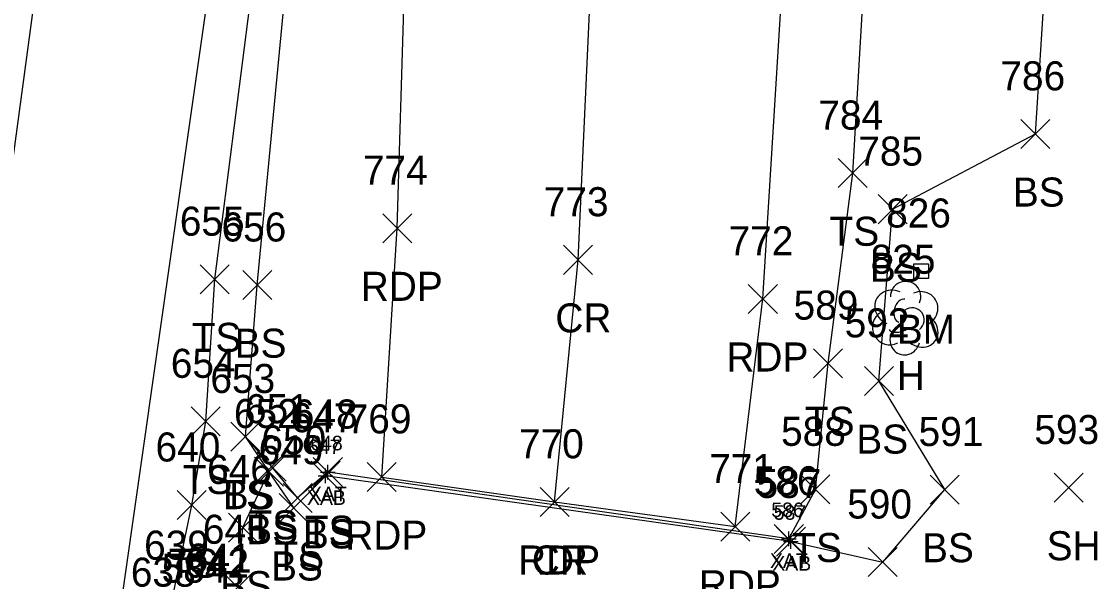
# Model space of a CAD drawing. Extents: x 1482574 to 1485769, y 580696 to 595649.
# Drawn here: x 1483671.3 to 1483745.3, y 584459.2 to 584497.7 of the extents above; entities that cross this region are included whole.
import ezdxf

# ---------------------------------------------------------------- set-up
doc = ezdxf.new("R2010")
doc.units = 0
for name, color, linetype in [('B_A', 7, 'Continuous'), ('B_I', 7, 'Continuous'), ('B_TIC', 7, 'Continuous'), ('BSUBM', 7, 'Continuous'), ('C_A', 7, 'Continuous'), ('C_I', 7, 'Continuous'), ('CPBM', 7, 'Continuous'), ('D_I', 7, 'Continuous'), ('L_A', 7, 'Continuous'), ('L_I', 7, 'Continuous'), ('L_TIC', 7, 'Continuous'), ('LELB', 7, 'Continuous'), ('LTD', 7, 'Continuous'), ('P_A', 7, 'Continuous'), ('P_I', 7, 'Continuous'), ('P_TIC', 7, 'Continuous'), ('PET', 7, 'Continuous'), ('PRC', 7, 'Continuous')]:
    doc.layers.add(name, color=color, linetype=linetype)

msp = doc.modelspace()

# ---------------------------------------------------------------- linework, layer by layer
at = {"layer": 'B_TIC'}
for p, q in [((1483692.191, 584466.458), (1483692.266, 584466.458)), ((1483692.345, 584466.713), (1483692.421, 584466.713)), ((1483724.085, 584462.117), (1483724.161, 584462.117)), ((1483724.226, 584461.933), (1483724.301, 584461.933))]:
    msp.add_line(p, q, dxfattribs=at)
for points in [[(1483692.342, 584466.213), (1483692.342, 584467.213)], [(1483691.687, 584466.458), (1483692.687, 584466.458)], [(1483691.842, 584466.713), (1483692.842, 584466.713)], [(1483692.187, 584465.958), (1483692.187, 584466.958)], [(1483723.582, 584462.117), (1483724.582, 584462.117)], [(1483724.082, 584461.617), (1483724.082, 584462.617)], [(1483724.222, 584461.433), (1483724.222, 584462.433)], [(1483723.722, 584461.933), (1483724.722, 584461.933)]]:
    msp.add_lwpolyline(points, dxfattribs=at)
at = {"layer": 'BSUBM'}
for points in [[(1483724.222, 584461.933), (1483692.187, 584466.458)], [(1483724.082, 584462.117), (1483692.342, 584466.713)]]:
    msp.add_lwpolyline(points, dxfattribs=at)
at = {"layer": 'CPBM'}
for p, q in [((1483732.691, 584480.051), (1483732.691, 584481.052)), ((1483732.691, 584481.052), (1483733.691, 584481.052)), ((1483733.194, 584480.552), (1483733.194, 584480.552)), ((1483733.194, 584480.552), (1483733.194, 584480.552)), ((1483733.691, 584481.052), (1483733.691, 584480.051)), ((1483733.691, 584480.051), (1483732.691, 584480.051))]:
    msp.add_line(p, q, dxfattribs=at)
at = {"layer": 'L_TIC'}
for points in [[(1483740.06, 584488.994), (1483742.06, 584490.994)], [(1483742.06, 584488.994), (1483740.06, 584490.994)], [(1483727.475, 584486.296), (1483729.475, 584488.296)], [(1483729.475, 584486.296), (1483727.475, 584488.296)], [(1483730.223, 584483.814), (1483732.223, 584485.814)], [(1483732.223, 584483.814), (1483730.223, 584485.814)], [(1483683.56, 584478.99), (1483685.56, 584480.99)], [(1483685.56, 584478.99), (1483683.56, 584480.99)], [(1483686.487, 584478.59), (1483688.487, 584480.59)], [(1483688.487, 584478.59), (1483686.487, 584480.59)], [(1483686.487, 584478.59), (1483688.487, 584480.59)], [(1483688.487, 584478.59), (1483686.487, 584480.59)], [(1483725.778, 584473.21), (1483727.778, 584475.21)], [(1483727.778, 584473.21), (1483725.778, 584475.21)], [(1483729.285, 584471.988), (1483731.285, 584473.988)], [(1483731.285, 584471.988), (1483729.285, 584473.988)], [(1483682.941, 584469.204), (1483684.941, 584471.204)], [(1483684.941, 584469.204), (1483682.941, 584471.204)], [(1483685.666, 584468.162), (1483687.666, 584470.162)], [(1483687.666, 584468.162), (1483685.666, 584470.162)], [(1483685.666, 584468.162), (1483687.666, 584470.162)], [(1483687.666, 584468.162), (1483685.666, 584470.162)], [(1483687.48, 584466.081), (1483689.48, 584468.081)], [(1483689.48, 584466.081), (1483687.48, 584468.081)], [(1483687.287, 584465.751), (1483689.287, 584467.751)], [(1483689.287, 584465.751), (1483687.287, 584467.751)], [(1483687.287, 584465.751), (1483689.287, 584467.751)], [(1483689.287, 584465.751), (1483687.287, 584467.751)], [(1483691.187, 584465.458), (1483693.187, 584467.458)], [(1483693.187, 584465.458), (1483691.187, 584467.458)], [(1483691.342, 584465.713), (1483693.342, 584467.713)], [(1483693.342, 584465.713), (1483691.342, 584467.713)], [(1483724.907, 584464.522), (1483726.907, 584466.522)], [(1483726.907, 584464.522), (1483724.907, 584466.522)], [(1483733.809, 584464.509), (1483735.809, 584466.509)], [(1483735.809, 584464.509), (1483733.809, 584466.509)], [(1483742.344, 584464.645), (1483744.344, 584466.645)], [(1483744.344, 584464.645), (1483742.344, 584466.645)], [(1483689.264, 584463.932), (1483691.264, 584465.932)], [(1483691.264, 584463.932), (1483689.264, 584465.932)], [(1483681.978, 584463.444), (1483683.978, 584465.444)], [(1483683.978, 584463.444), (1483681.978, 584465.444)], [(1483688.995, 584463.25), (1483690.995, 584465.25)], [(1483690.995, 584463.25), (1483688.995, 584465.25)], [(1483685.493, 584461.897), (1483687.493, 584463.897)], [(1483687.493, 584461.897), (1483685.493, 584463.897)], [(1483723.082, 584461.117), (1483725.082, 584463.117)], [(1483725.082, 584461.117), (1483723.082, 584463.117)], [(1483723.222, 584460.933), (1483725.222, 584462.933)], [(1483725.222, 584460.933), (1483723.222, 584462.933)], [(1483729.548, 584459.517), (1483731.548, 584461.517)], [(1483731.548, 584459.517), (1483729.548, 584461.517)], [(1483685.145, 584457.78), (1483687.145, 584459.78)], [(1483687.145, 584457.78), (1483685.145, 584459.78)], [(1483685.145, 584457.78), (1483687.145, 584459.78)], [(1483687.145, 584457.78), (1483685.145, 584459.78)]]:
    msp.add_lwpolyline(points, dxfattribs=at)
at = {"layer": 'LELB'}
for points in [[(1483724.082, 584462.117), (1483725.907, 584465.522), (1483726.778, 584474.21), (1483728.475, 584487.296), (1483730.22, 584517.102), (1483728.729, 584547.617), (1483723.607, 584570.881), (1483719.45, 584596.971), (1483717.38, 584631.511), (1483714.685, 584660.925), (1483714.05, 584681.93), (1483713.087, 584704.559), (1483712.732, 584748.378), (1483712.013, 584794.586), (1483710.894, 584850.574), (1483709.946, 584870.249), (1483710.982, 584893.468), (1483715.858, 584918.494)], [(1483724.222, 584461.933), (1483730.548, 584460.517), (1483734.809, 584465.509), (1483730.285, 584472.988), (1483731.223, 584484.814), (1483741.06, 584489.994), (1483742.648, 584514.966), (1483736.695, 584548.75), (1483727.528, 584570.579), (1483723.616, 584597.151), (1483724.565, 584630.748), (1483719.544, 584660.803), (1483719.138, 584682.266)], [(1483681.19, 584455.828), (1483682.978, 584464.444), (1483683.941, 584470.204), (1483684.56, 584479.99), (1483687.932, 584506.357), (1483690.535, 584538.953), (1483691.613, 584557.814)], [(1483687.487, 584479.59), (1483690.015, 584506.184), (1483692.728, 584538.566), (1483691.613, 584557.814)], [(1483686.145, 584458.78), (1483686.493, 584462.897), (1483688.287, 584466.751), (1483686.666, 584469.162), (1483687.487, 584479.59)], [(1483692.342, 584466.713), (1483690.264, 584464.932), (1483688.48, 584467.081), (1483686.666, 584469.162)], [(1483692.187, 584466.458), (1483689.995, 584464.25), (1483688.287, 584466.751)]]:
    msp.add_lwpolyline(points, dxfattribs=at)
at = {"layer": 'LTD'}
msp.add_line((1483732.075, 584477.368), (1483732.075, 584477.368), dxfattribs=at)
msp.add_line((1483732.075, 584477.368), (1483732.075, 584477.368), dxfattribs=at)
msp.add_arc((1483732.122, 584478.802), 1.047, 335.52715, 180.95627, dxfattribs=at)
for centre, major_axis, ratio, start_param, end_param in [((1483731.283, 584478.034), (1.21, -0.512), 0.895232, 1.570796, 4.712389), ((1483733.116, 584477.951), (-1.141, -0.483), 0.949671, 1.570796, 4.712389), ((1483731.866, 584477.826), (-0.208, -0.792), 0.645439, 3.141593, 6.283185), ((1483730.992, 584476.659), (0.584, -1.042), 0.959034, 3.141593, 6.283185), ((1483732.575, 584477.201), (-0.5, 0.667), 0.989748, 3.141593, 6.283185), ((1483733.075, 584476.535), (-1.09, 0.792), 0.841452, 1.570796, 4.712389), ((1483732.075, 584475.868), (0.265, 1.061), 0.942809, 1.570796, 4.712389), ((1483731.617, 584476.618), (-0.625, -0.083), 0.423636, 0, 3.141593)]:
    msp.add_ellipse(centre, major_axis=major_axis, ratio=ratio, start_param=start_param, end_param=end_param, dxfattribs=at)
at = {"layer": 'P_TIC'}
for points in [[(1483696.12, 584482.504), (1483698.12, 584484.504)], [(1483698.12, 584482.504), (1483696.12, 584484.504)], [(1483708.571, 584480.329), (1483710.571, 584482.329)], [(1483710.571, 584480.329), (1483708.571, 584482.329)], [(1483721.292, 584477.639), (1483723.292, 584479.639)], [(1483723.292, 584477.639), (1483721.292, 584479.639)], [(1483695.056, 584465.376), (1483697.056, 584467.376)], [(1483697.056, 584465.376), (1483695.056, 584467.376)], [(1483695.056, 584465.376), (1483697.056, 584467.376)], [(1483697.056, 584465.376), (1483695.056, 584467.376)], [(1483706.951, 584463.664), (1483708.951, 584465.664)], [(1483708.951, 584463.664), (1483706.951, 584465.664)], [(1483706.951, 584463.664), (1483708.951, 584465.664)], [(1483708.951, 584463.664), (1483706.951, 584465.664)], [(1483719.395, 584461.958), (1483721.395, 584463.958)], [(1483721.395, 584461.958), (1483719.395, 584463.958)]]:
    msp.add_lwpolyline(points, dxfattribs=at)
at = {"layer": 'PET'}
for points in [[(1483696.056, 584466.376), (1483697.12, 584483.504), (1483698.012, 584513.546), (1483697.99, 584538.325), (1483692.768, 584571.081), (1483691.881, 584578.266), (1483689.767, 584596.032), (1483686.09, 584631.801), (1483683.963, 584666.864), (1483683.24, 584704.064), (1483683.213, 584748.185), (1483682.284, 584793.898), (1483680.781, 584850.652), (1483678.799, 584902.917), (1483672.318, 584970.596), (1483669.676, 585004.195), (1483663.897, 585069.156), (1483661.293, 585125.323), (1483656.933, 585178.041), (1483653.345, 585225.148), (1483650.718, 585274.261)], [(1483696.056, 584466.376), (1483707.951, 584464.664), (1483720.395, 584462.958), (1483722.292, 584478.639), (1483724.313, 584511.602), (1483723.072, 584540.322), (1483718.492, 584572.42), (1483715.109, 584598.08), (1483710.676, 584631.833), (1483709.971, 584663.072), (1483708.89, 584702.48), (1483708.909, 584747.528), (1483707.882, 584794.212), (1483706.23, 584850.223), (1483704.432, 584903.519), (1483701.567, 584959.324), (1483696.138, 585000.989), (1483691.089, 585058.765), (1483691.123, 585078.996), (1483685.882, 585127.238), (1483682.764, 585180.384), (1483679.267, 585226.938), (1483675.802, 585274.419)], [(1483647.153, 584246.073), (1483652.116, 584273.969), (1483655.812, 584298.407), (1483662.078, 584336.279), (1483668.628, 584381.649), (1483673.206, 584417.173), (1483676.95, 584449.388), (1483685.132, 584506.852), (1483688.619, 584539.157), (1483690.513, 584562.402), (1483689.874, 584577.413), (1483687.032, 584596.302), (1483683.383, 584631.912), (1483681.394, 584667.042), (1483680.097, 584704.07), (1483680.199, 584748.578), (1483679.791, 584793.534), (1483679.214, 584850.638), (1483677.205, 584902.59), (1483672.318, 584970.596)]]:
    msp.add_lwpolyline(points, dxfattribs=at)
at = {"layer": 'PRC'}
for points in [[(1483707.951, 584464.664), (1483709.571, 584481.329), (1483711.018, 584513.103), (1483710.869, 584539.52), (1483705.796, 584571.84), (1483702.272, 584596.863), (1483698.558, 584629.802), (1483696.986, 584664.785), (1483696.345, 584703.625), (1483696.113, 584746.951), (1483694.967, 584793.896), (1483693.554, 584850.212), (1483691.778, 584903.164), (1483687.151, 584966.026), (1483684.726, 584995.278), (1483678.253, 585070.791), (1483674.343, 585126.265), (1483669.53, 585178.968), (1483666.462, 585226.521), (1483663.263, 585274.777)], [(1483620.6, 584139.065), (1483622.763, 584151.247), (1483629.797, 584198.381), (1483635.338, 584238.334), (1483640.976, 584275.018), (1483645.104, 584300.758), (1483651.328, 584343.687), (1483657.044, 584382.594), (1483662.408, 584419.091), (1483666.56, 584457.849), (1483673.341, 584508.06), (1483676.923, 584541.038), (1483679.396, 584571.577), (1483681.278, 584596.253), (1483683.383, 584631.912)]]:
    msp.add_lwpolyline(points, dxfattribs=at)

# ---------------------------------------------------------------- texts
at = {"layer": 'B_A'}
for s, p in [('XAT', (1483691.047, 584464.713)), ('XAB', (1483690.908, 584464.458)), ('XAT', (1483722.786, 584460.117)), ('XAB', (1483722.943, 584459.933))]:
    msp.add_text(s, height=1, dxfattribs=at).set_placement(p)
at = {"layer": 'B_I'}
for s, p in [('647', (1483690.982, 584467.958)), ('648', (1483691.137, 584468.213)), ('586', (1483722.873, 584463.617)), ('587', (1483723.041, 584463.433))]:
    msp.add_text(s, height=1, dxfattribs=at).set_placement(p)
at = {"layer": 'C_A'}
msp.add_text('BM', height=2, dxfattribs=at).set_placement((1483731.509, 584475.552))
at = {"layer": 'C_I'}
msp.add_text('826', height=2, dxfattribs=at).set_placement((1483730.777, 584483.552))
at = {"layer": 'D_I'}
for s, p in [('639', (1483679.693, 584460.685)), ('642', (1483682.459, 584459.454)), ('641', (1483682.636, 584459.796)), ('638', (1483678.78, 584458.828))]:
    msp.add_text(s, height=2, dxfattribs=at).set_placement(p)
at = {"layer": 'L_A'}
for s, p in [('BS', (1483739.501, 584484.994)), ('TS', (1483726.885, 584482.296)), ('BS', (1483729.664, 584479.814)), ('TS', (1483682.969, 584474.99)), ('BS', (1483685.928, 584474.59)), ('BS', (1483685.928, 584474.59)), ('H', (1483731.508, 584472.368)), ('TS', (1483725.187, 584469.21)), ('BS', (1483728.726, 584467.988)), ('TS', (1483682.35, 584465.204)), ('TS', (1483685.075, 584464.162)), ('BS', (1483685.107, 584464.162)), ('BS', (1483686.728, 584461.751)), ('BS', (1483686.728, 584461.751)), ('TS', (1483686.89, 584462.081)), ('TS', (1483690.751, 584461.713)), ('BS', (1483690.628, 584461.458)), ('TS', (1483724.317, 584460.522)), ('BS', (1483733.25, 584460.509)), ('SH', (1483741.832, 584460.645)), ('TS', (1483681.387, 584459.444)), ('BS', (1483688.436, 584459.25)), ('TS', (1483688.673, 584459.932)), ('BS', (1483684.934, 584457.897))]:
    msp.add_text(s, height=2, dxfattribs=at).set_placement(p)
at = {"layer": 'L_I'}
for s, p in [('786', (1483738.643, 584492.994)), ('784', (1483726.113, 584490.296)), ('785', (1483728.86, 584487.814)), ('655', (1483682.15, 584482.99)), ('656', (1483685.022, 584482.59)), ('656', (1483685.022, 584482.59)), ('825', (1483729.713, 584480.368)), ('589', (1483724.407, 584477.21)), ('592', (1483727.923, 584475.988)), ('654', (1483681.531, 584473.204)), ('653', (1483684.256, 584472.162)), ('653', (1483684.256, 584472.162)), ('652', (1483685.878, 584469.751)), ('652', (1483685.878, 584469.751)), ('651', (1483686.638, 584470.081)), ('648', (1483689.933, 584469.713)), ('647', (1483689.778, 584469.458)), ('588', (1483723.545, 584468.522)), ('591', (1483733.014, 584468.509)), ('593', (1483740.982, 584468.645)), ('640', (1483680.482, 584467.444)), ('650', (1483687.768, 584467.932)), ('649', (1483687.578, 584467.25)), ('646', (1483684.028, 584465.897)), ('586', (1483721.664, 584465.117)), ('587', (1483721.86, 584464.933)), ('590', (1483728.099, 584463.517)), ('645', (1483683.736, 584461.78)), ('645', (1483683.736, 584461.78)), ('638', (1483678.78, 584458.828)), ('584', (1483680.895, 584459.096)), ('584', (1483680.895, 584459.096))]:
    msp.add_text(s, height=2, dxfattribs=at).set_placement(p)
at = {"layer": 'P_A'}
for s, p in [('RDP', (1483694.608, 584478.504)), ('CR', (1483708.004, 584476.329)), ('RDP', (1483719.78, 584473.639)), ('RDP', (1483693.544, 584461.376)), ('RDP', (1483693.544, 584461.376)), ('RDP', (1483705.439, 584459.664)), ('CR', (1483706.384, 584459.664)), ('RDP', (1483717.883, 584457.958))]:
    msp.add_text(s, height=2, dxfattribs=at).set_placement(p)
at = {"layer": 'P_I'}
for s, p in [('774', (1483694.757, 584486.504)), ('773', (1483707.209, 584484.329)), ('772', (1483719.93, 584481.639)), ('769', (1483693.639, 584469.376)), ('769', (1483693.639, 584469.376)), ('770', (1483705.502, 584467.664)), ('770', (1483705.502, 584467.664)), ('771', (1483718.599, 584465.958))]:
    msp.add_text(s, height=2, dxfattribs=at).set_placement(p)

doc.saveas('drawing.dxf')
